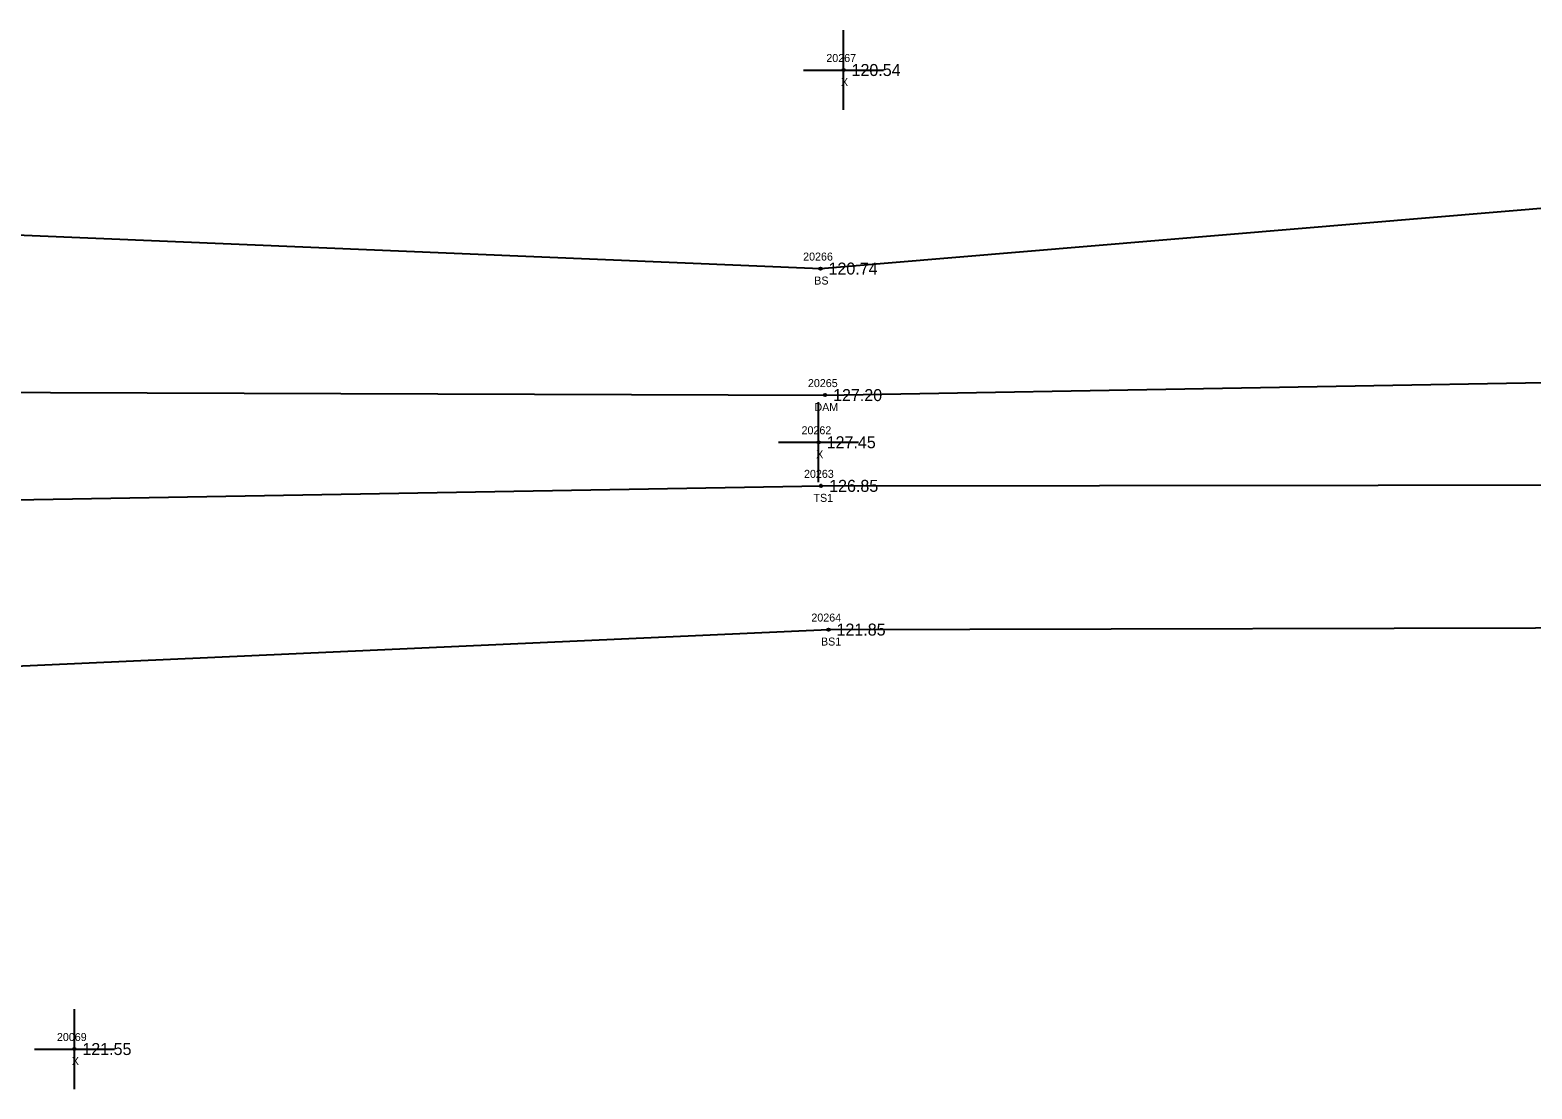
# Model space of a CAD drawing. Extents: x 2375812 to 2377225, y 1024470 to 1025135.
# Drawn here: x 2376214.8 to 2376402.6, y 1024989.2 to 1025121.6 of the extents above; entities that cross this region are included whole.
import ezdxf

# ---------------------------------------------------------------- set-up
doc = ezdxf.new("R2010")
doc.units = 0
for name, color, linetype in [('RD_DTM_BkLn2', 7, 'Continuous'), ('RD_DTM_BkLn_txCode', 7, 'Continuous'), ('RD_EX_Dam', 7, 'Continuous'), ('RD_EX_Dam_txCode', 7, 'Continuous'), ('RD_EX_Misc', 7, 'Continuous'), ('RD_EX_Misc_txCode', 7, 'Continuous'), ('RD_EX_TX_Dam_ELEV', 7, 'Continuous'), ('RD_EX_TX_Misc_ELEV', 7, 'Continuous'), ('RD_SMD_Locator', 7, 'Continuous')]:
    doc.layers.add(name, color=color, linetype=linetype)

msp = doc.modelspace()

# ---------------------------------------------------------------- linework, layer by layer
at = {"layer": 'RD_DTM_BkLn2'}
for points in [[(2375847.51, 1025092.15), (2375876.46, 1025088.72), (2375981.63, 1025092.39), (2376090.5, 1025090.54), (2376205.11, 1025096.35), (2376313.64, 1025091.79), (2376415.11, 1025100.3), (2376448.24, 1025100.64), (2376465.02, 1025111.39), (2376486.46, 1025115.19), (2376497.97, 1025114.18)], [(2375847.93, 1025050.33), (2375875.91, 1025056.72), (2375981.44, 1025060.56), (2376091.98, 1025062.38), (2376205.71, 1025062.75), (2376313.72, 1025064.62), (2376418.13, 1025064.73), (2376493.03, 1025062.01)], [(2375848.17, 1025037.34), (2375876.1, 1025042.73), (2375981.89, 1025042.57), (2376092.59, 1025040.39), (2376206.51, 1025041.77), (2376314.64, 1025046.65), (2376420.66, 1025046.91), (2376483.6, 1025044.87), (2376501.85, 1025058.56), (2376497.33, 1025064.77)]]:
    msp.add_lwpolyline(points, dxfattribs=at)
at = {"layer": 'RD_EX_Dam'}
msp.add_lwpolyline([(2375847.73, 1025068.2), (2375876.5, 1025071.72), (2375981.19, 1025074.08), (2376091.91, 1025074.48), (2376205.24, 1025076.35), (2376314.21, 1025075.97), (2376418.29, 1025077.81), (2376454.32, 1025078.43), (2376493.3, 1025082.7)], dxfattribs=at)
at = {"layer": 'RD_EX_Misc'}
for p, q in [((2376316.52, 1025111.62), (2376316.52, 1025121.62)), ((2376311.52, 1025116.62), (2376321.52, 1025116.62)), ((2376313.41, 1025065.07), (2376313.41, 1025075.07)), ((2376308.41, 1025070.07), (2376318.41, 1025070.07)), ((2376220.39, 1024989.2), (2376220.39, 1024999.2)), ((2376215.39, 1024994.2), (2376225.39, 1024994.2))]:
    msp.add_line(p, q, dxfattribs=at)
at = {"layer": 'RD_SMD_Locator'}
for centre in [(2376316.52, 1025116.62), (2376313.64, 1025091.79), (2376314.21, 1025075.97), (2376313.41, 1025070.07), (2376313.72, 1025064.62), (2376314.64, 1025046.65), (2376220.39, 1024994.2)]:
    msp.add_circle(centre, 0.15, dxfattribs=at)

# ---------------------------------------------------------------- texts
at = {"layer": 'RD_DTM_BkLn_txCode'}
for s, p in [('20266', (2376311.47, 1025092.79)), ('BS', (2376312.86, 1025089.79)), ('20263', (2376311.58, 1025065.62)), ('TS1', (2376312.76, 1025062.62)), ('20264', (2376312.5, 1025047.65)), ('BS1', (2376313.7, 1025044.65))]:
    msp.add_text(s, height=1, dxfattribs=at).set_placement(p)
at = {"layer": 'RD_EX_Dam_txCode'}
for s, p in [('20265', (2376312.07, 1025076.97)), ('DAM', (2376312.88, 1025073.97))]:
    msp.add_text(s, height=1, dxfattribs=at).set_placement(p)
at = {"layer": 'RD_EX_Misc_txCode'}
for s, p in [('20267', (2376314.37, 1025117.62)), ('X', (2376316.2, 1025114.62)), ('20262', (2376311.27, 1025071.07)), ('X', (2376313.1, 1025068.07)), ('20069', (2376218.21, 1024995.2)), ('X', (2376220.07, 1024992.2))]:
    msp.add_text(s, height=1, dxfattribs=at).set_placement(p)
at = {"layer": 'RD_EX_TX_Dam_ELEV'}
msp.add_text('127.20', height=1.5, dxfattribs=at).set_placement((2376315.21, 1025075.22))
at = {"layer": 'RD_EX_TX_Misc_ELEV'}
for s, p in [('120.54', (2376317.52, 1025115.87)), ('120.74', (2376314.64, 1025091.04)), ('127.45', (2376314.41, 1025069.32)), ('126.85', (2376314.72, 1025063.87)), ('121.85', (2376315.64, 1025045.9)), ('121.55', (2376221.39, 1024993.45))]:
    msp.add_text(s, height=1.5, dxfattribs=at).set_placement(p)

doc.saveas('drawing.dxf')
